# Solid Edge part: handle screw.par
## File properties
Title: Handle Screw
Author: Robert a Rhodes jr
Template: Normal.par
Last saved by: Rajat Kamboj
Revision: 18
Application: Solid Edge
Accuracy: 0.99
Material: aluminum
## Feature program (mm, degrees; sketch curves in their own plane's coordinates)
sketch for "unnamed Protrusion 1" plane through (0, 0, 0) normal (0, -1, 0) x-axis (1, 0, 0)
  circle centre (0, 0) radius 7.5
extrude "unnamed Protrusion 1" add finite 14 along +normal
sketch for "Hole_1" plane through (0, -14, 0) normal (0, -1, 0) x-axis (1, 0, 0)
  hole centre (0, 0) bore radius 4
hole "Hole_1" diameter 8 finite  VBottomAngle = 120 deg
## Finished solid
Body 1: solid body, 5 faces, 4 edges, 1 vertex.
  Faces by surface: cylinder 2, plane 2, cone 1
  Edges by curve: circle 4
Bounding box of the edges (mm): 15.000 x 14.000 x 15.000, from (-7.5, -14, -7.5) to (7.5, 0, 7.5).
Cylindrical faces by radius (mm): R4 x1, R7.5 x1
Conical faces (half-angle, radius in mm at the cone's reference point): 60 deg R4 x1
Planar faces by outward normal: +y 1, -y 1
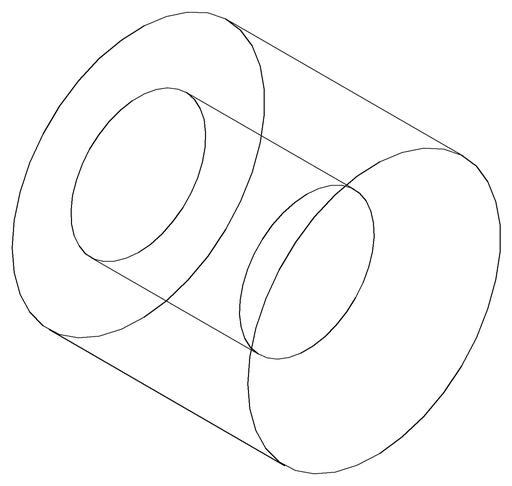
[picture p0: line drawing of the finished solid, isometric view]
